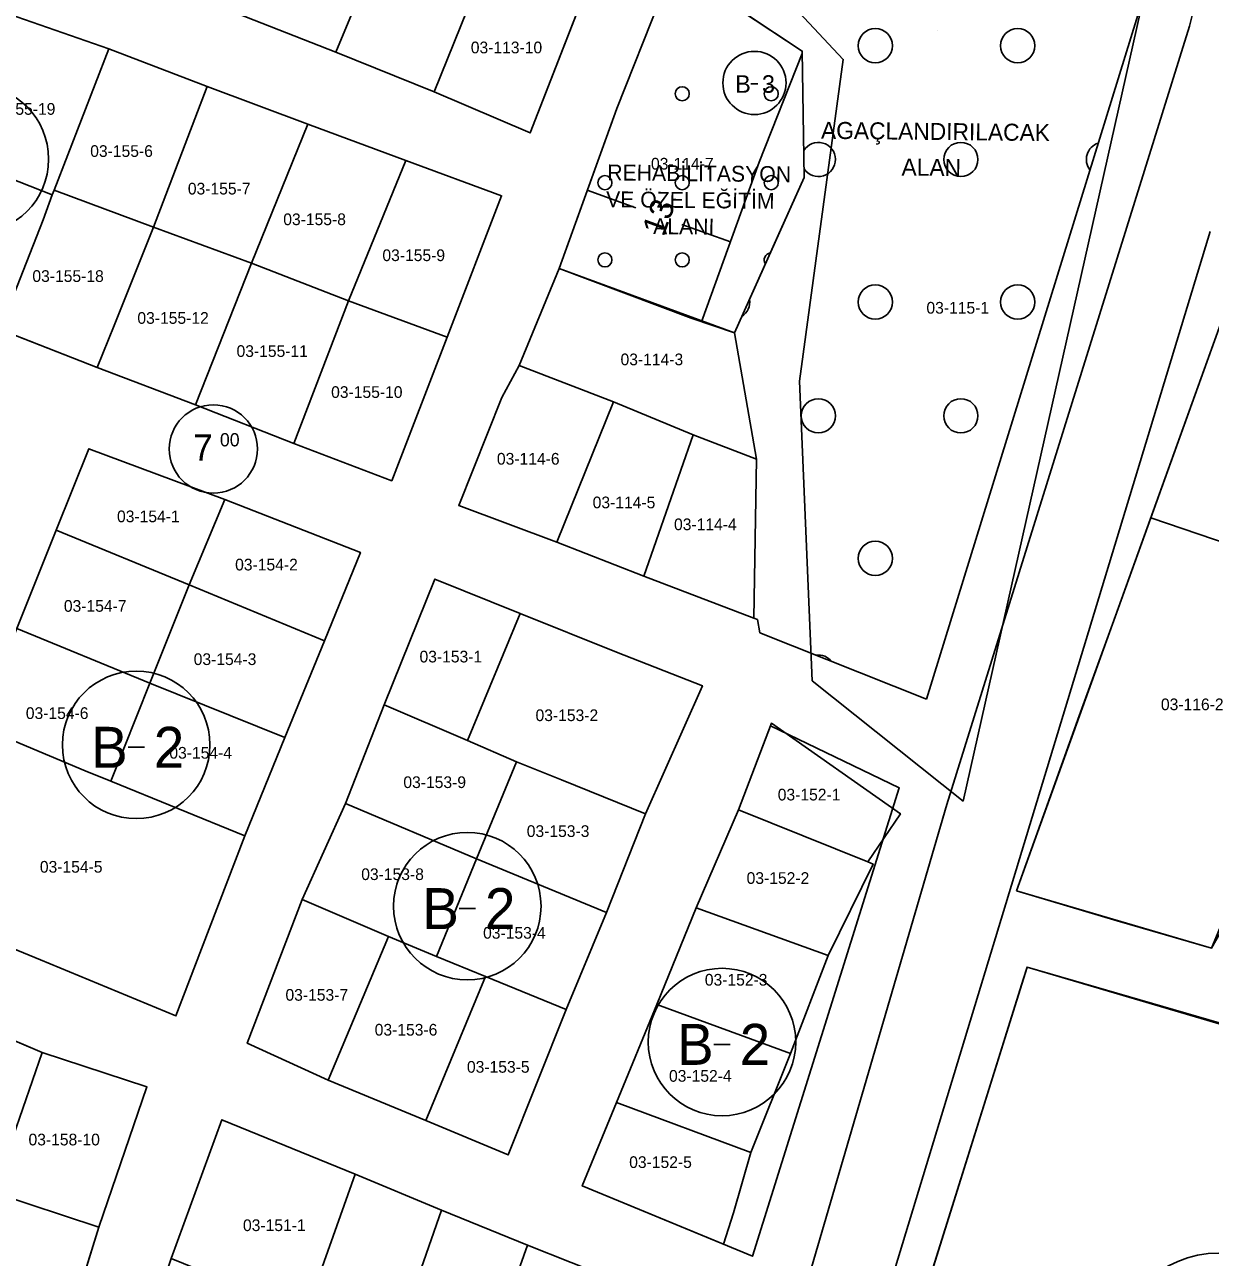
# Model space of a CAD drawing. Extents: x 413946 to 415528, y 4453939 to 4454944.
# Drawn here: x 414770 to 414871.3, y 4454188.1 to 4454293.5 of the extents above; entities that cross this region are included whole.
import ezdxf

# ---------------------------------------------------------------- set-up
doc = ezdxf.new("R2010")
doc.units = 0
for name, color, linetype in [('0_KADASTRO', 7, 'Continuous'), ('Level 20', 7, 'Continuous'), ('Level 27', 7, 'Continuous'), ('Level 28', 7, 'Continuous'), ('Level 29', 7, 'Continuous'), ('Level 33', 7, 'Continuous'), ('Level 34', 7, 'Continuous'), ('Level 42', 7, 'Continuous'), ('Level 43', 7, 'Continuous'), ('Level 54', 7, 'Continuous'), ('Level 62', 7, 'Continuous'), ('SEMBOL', 7, 'Continuous'), ('SNR_FONKSIYON', 7, 'Continuous'), ('SNR_YAPIYAK', 7, 'Continuous')]:
    doc.layers.add(name, color=color, linetype=linetype)

msp = doc.modelspace()

# ---------------------------------------------------------------- linework, layer by layer
at = {"layer": '0_KADASTRO'}
for points in [[(414832.03, 4454298.98), (414838.1, 4454302.72), (414846.56, 4454310.73), (414850.2, 4454326.97), (414865.66, 4454296.04), (414850.19, 4454227.12), (414837.29, 4454237.41), (414836.22, 4454262.99), (414839.96, 4454290.49)], [(414788.17, 4454294.42), (414793.15, 4454306.88), (414801.8, 4454303.57), (414796.61, 4454291.12)], [(414796.61, 4454291.12), (414801.8, 4454303.57), (414810.12, 4454300.36), (414805, 4454287.71)], [(414805, 4454287.71), (414810.12, 4454300.36), (414818.3, 4454297.33), (414813.2, 4454284.21)], [(414815.68, 4454272.63), (414818.73, 4454281.09), (414820.62, 4454286.31), (414824.34, 4454295.73), (414827.17, 4454297.35), (414836.45, 4454291.2), (414836.62, 4454280.41), (414834.34, 4454275.32), (414830.66, 4454267.12), (414826.97, 4454268.38)], [(414763.9, 4454282.25), (414764.12, 4454282.88), (414765.37, 4454286.01), (414768.71, 4454294.36), (414777.22, 4454291.39), (414772.55, 4454279.33), (414772.39, 4454278.91)], [(414772.55, 4454279.33), (414777.22, 4454291.39), (414785.63, 4454288.19), (414781.05, 4454276.16)], [(414781.05, 4454276.16), (414785.63, 4454288.19), (414794.22, 4454284.95), (414789.42, 4454273.08)], [(414789.42, 4454273.08), (414794.22, 4454284.95), (414802.59, 4454281.85), (414797.69, 4454269.86)], [(414756.22, 4454272.04), (414760.92, 4454283.99), (414764.12, 4454282.88), (414763.9, 4454282.25), (414772.39, 4454278.91), (414771.6, 4454276.78), (414767.95, 4454267.42), (414767.49, 4454267.6), (414758.76, 4454271.04)], [(414797.69, 4454269.86), (414802.59, 4454281.85), (414810.77, 4454278.84), (414806.13, 4454266.76)], [(414767.95, 4454267.42), (414771.6, 4454276.78), (414772.39, 4454278.91), (414772.55, 4454279.33), (414781.05, 4454276.16), (414777.69, 4454267.75), (414776.23, 4454264.18)], [(414776.23, 4454264.18), (414777.69, 4454267.75), (414781.05, 4454276.16), (414789.42, 4454273.08), (414784.62, 4454260.99)], [(414784.62, 4454260.99), (414789.42, 4454273.08), (414797.69, 4454269.86), (414793.03, 4454257.69)], [(414812.27, 4454264.34), (414815.68, 4454272.63), (414826.97, 4454268.38), (414830.66, 4454267.12), (414832.54, 4454256.34), (414827.14, 4454258.41), (414820.34, 4454261.23)], [(414793.03, 4454257.69), (414797.69, 4454269.86), (414806.13, 4454266.76), (414801.39, 4454254.49)], [(414866.22, 4454251.33), (414873.1, 4454270.41), (414882.7, 4454267.64), (414875.68, 4454248.11)], [(414854.74, 4454219.46), (414860.12, 4454234.41), (414863.17, 4454242.88), (414866.22, 4454251.33), (414875.68, 4454248.11), (414882.7, 4454267.64), (414886.54, 4454266.53), (414890.57, 4454260.69), (414884.15, 4454245.23), (414880.7, 4454236.93), (414877.25, 4454228.62), (414871.98, 4454215.94), (414871.41, 4454214.55), (414863.36, 4454216.9)], [(414807.11, 4454252.37), (414810.8, 4454261.62), (414812.27, 4454264.34), (414820.34, 4454261.23), (414815.48, 4454249.26)], [(414815.48, 4454249.26), (414820.34, 4454261.23), (414827.14, 4454258.41), (414822.93, 4454246.35)], [(414822.93, 4454246.35), (414827.14, 4454258.41), (414832.54, 4454256.34), (414832.32, 4454242.75)], [(414772.73, 4454250.28), (414775.51, 4454257.23), (414787.12, 4454252.89), (414784.08, 4454245.59)], [(414784.08, 4454245.59), (414787.12, 4454252.89), (414798.71, 4454248.37), (414795.63, 4454240.82)], [(414769.36, 4454241.86), (414772.73, 4454250.28), (414784.08, 4454245.59), (414780.73, 4454237.2)], [(414780.73, 4454237.2), (414784.08, 4454245.59), (414795.63, 4454240.82), (414792.25, 4454232.56)], [(414800.74, 4454235.36), (414805.08, 4454246.09), (414812.37, 4454243.14), (414807.85, 4454232.29)], [(414807.85, 4454232.29), (414812.37, 4454243.14), (414820.6, 4454239.86), (414827.92, 4454236.98), (414823.05, 4454226.04), (414815.88, 4454228.93), (414812.04, 4454230.47)], [(414766.04, 4454233.56), (414769.36, 4454241.86), (414780.73, 4454237.2), (414777.4, 4454228.84), (414775.2, 4454229.71)], [(414777.4, 4454228.84), (414780.73, 4454237.2), (414792.25, 4454232.56), (414788.83, 4454224.17)], [(414797.44, 4454226.92), (414800.74, 4454235.36), (414807.85, 4454232.29), (414812.04, 4454230.47), (414808.64, 4454222.18)], [(414831.02, 4454226.38), (414833.82, 4454233.78), (414844.84, 4454226.04), (414842.05, 4454221.95)], [(414759.79, 4454218.33), (414762.79, 4454225.66), (414766.04, 4454233.56), (414775.2, 4454229.71), (414777.4, 4454228.84), (414788.83, 4454224.17), (414785.8, 4454216.2), (414782.95, 4454208.77), (414771.37, 4454213.55)], [(414808.64, 4454222.18), (414812.04, 4454230.47), (414815.88, 4454228.93), (414823.05, 4454226.04), (414819.72, 4454217.62)], [(414793.73, 4454218.72), (414797.44, 4454226.92), (414808.64, 4454222.18), (414805.22, 4454213.86), (414801.1, 4454215.56)], [(414827.39, 4454218), (414831.02, 4454226.38), (414842.05, 4454221.95), (414842.5, 4454221.74), (414838.66, 4454213.93)], [(414805.22, 4454213.86), (414808.64, 4454222.18), (414819.72, 4454217.62), (414816.28, 4454209.32), (414809.4, 4454212.13)], [(414789.05, 4454206.43), (414793.73, 4454218.72), (414801.1, 4454215.56), (414795.95, 4454203.28)], [(414824.03, 4454209.74), (414827.39, 4454218), (414838.66, 4454213.93), (414835.46, 4454205.55)], [(414795.95, 4454203.28), (414801.1, 4454215.56), (414805.22, 4454213.86), (414809.4, 4454212.13), (414804.29, 4454199.85)], [(414837.9, 4454152.37), (414841.59, 4454167.97), (414850.85, 4454197.57), (414855.33, 4454211.88), (414855.66, 4454212.94), (414874.02, 4454207.6), (414876.77, 4454206.53), (414913.67, 4454192.21), (414892.7, 4454138.17)], [(414804.29, 4454199.85), (414809.4, 4454212.13), (414816.28, 4454209.32), (414811.34, 4454196.9)], [(414820.58, 4454201.37), (414824.03, 4454209.74), (414835.46, 4454205.55), (414832.06, 4454197.11)], [(414758.86, 4454196.63), (414763.25, 4454209.19), (414771.53, 4454205.64), (414767.38, 4454193.69)], [(414767.38, 4454193.69), (414771.53, 4454205.64), (414780.48, 4454202.71), (414776.36, 4454190.71)], [(414817.66, 4454194.25), (414820.58, 4454201.37), (414832.06, 4454197.11), (414830.57, 4454191.94), (414829.72, 4454189.27)], [(414782.54, 4454188.05), (414786.88, 4454199.9), (414798.27, 4454195.26), (414794.06, 4454183.37), (414789.48, 4454185.23)], [(414794.06, 4454183.37), (414798.27, 4454195.26), (414805.65, 4454192.19), (414801.51, 4454180.34), (414798.22, 4454181.68)], [(414763.1, 4454181.29), (414767.38, 4454193.69), (414776.36, 4454190.71), (414772.34, 4454177.79)], [(414801.51, 4454180.34), (414805.65, 4454192.19), (414812.97, 4454189.19), (414808.79, 4454177.39), (414807.52, 4454177.9)], [(414808.79, 4454177.39), (414812.97, 4454189.19), (414820.45, 4454186.23), (414816.3, 4454174.34)]]:
    msp.add_lwpolyline(points, close=True, dxfattribs=at)
at = {"layer": 'Level 20'}
for p, q in [((414818.09, 4454279.31), (414822.23, 4454277.82)), ((414830.32, 4454274.9), (414826.18, 4454276.39))]:
    msp.add_line(p, q, dxfattribs=at)
at = {"layer": 'Level 27'}
for p, q in [((414823.57, 4454310.85), (414813.2, 4454284.21)), ((414820.62, 4454286.31), (414824.34, 4454295.73)), ((414768.71, 4454294.36), (414777.22, 4454291.39)), ((414796.61, 4454291.12), (414788.17, 4454294.42)), ((414777.22, 4454291.39), (414785.63, 4454288.19)), ((414805, 4454287.71), (414796.61, 4454291.12)), ((414785.63, 4454288.19), (414794.22, 4454284.95)), ((414813.2, 4454284.21), (414805, 4454287.71)), ((414815.68, 4454272.63), (414820.62, 4454286.31)), ((414794.22, 4454284.95), (414802.59, 4454281.85)), ((414802.59, 4454281.85), (414810.77, 4454278.84)), ((414810.77, 4454278.84), (414806.13, 4454266.76)), ((414812.27, 4454264.34), (414815.68, 4454272.63)), ((414776.23, 4454264.18), (414767.49, 4454267.6)), ((414806.13, 4454266.76), (414801.39, 4454254.49)), ((414810.8, 4454261.62), (414812.27, 4454264.34)), ((414784.62, 4454260.99), (414776.23, 4454264.18)), ((414807.11, 4454252.37), (414810.8, 4454261.62)), ((414793.03, 4454257.69), (414784.62, 4454260.99)), ((414772.73, 4454250.28), (414775.51, 4454257.23)), ((414775.51, 4454257.23), (414787.12, 4454252.89)), ((414801.39, 4454254.49), (414793.03, 4454257.69)), ((414787.12, 4454252.89), (414798.71, 4454248.37)), ((414815.48, 4454249.26), (414807.11, 4454252.37)), ((414769.36, 4454241.86), (414772.73, 4454250.28)), ((414822.93, 4454246.35), (414815.48, 4454249.26)), ((414798.71, 4454248.37), (414795.63, 4454240.82)), ((414800.74, 4454235.36), (414805.08, 4454246.09)), ((414805.08, 4454246.09), (414812.37, 4454243.14)), ((414832.32, 4454242.75), (414822.93, 4454246.35)), ((414812.37, 4454243.14), (414820.6, 4454239.86)), ((414832.62, 4454242.63), (414832.32, 4454242.75)), ((414795.63, 4454240.82), (414792.25, 4454232.56)), ((414820.6, 4454239.86), (414827.92, 4454236.98)), ((414827.92, 4454236.98), (414823.05, 4454226.04)), ((414797.44, 4454226.92), (414800.74, 4454235.36)), ((414831.02, 4454226.38), (414833.73, 4454233.55)), ((414833.73, 4454233.55), (414844.74, 4454228.27)), ((414792.25, 4454232.56), (414788.83, 4454224.17)), ((414793.73, 4454218.72), (414797.44, 4454226.92)), ((414823.05, 4454226.04), (414819.72, 4454217.62)), ((414827.39, 4454218), (414831.02, 4454226.38)), ((414788.83, 4454224.17), (414785.8, 4454216.2)), ((414771.37, 4454213.55), (414759.79, 4454218.33)), ((414789.05, 4454206.43), (414793.73, 4454218.72)), ((414824.03, 4454209.74), (414827.39, 4454218)), ((414819.72, 4454217.62), (414816.28, 4454209.32)), ((414785.8, 4454216.2), (414782.95, 4454208.77)), ((414782.95, 4454208.77), (414771.37, 4454213.55)), ((414820.58, 4454201.37), (414824.03, 4454209.74)), ((414763.25, 4454209.19), (414771.53, 4454205.64)), ((414816.28, 4454209.32), (414811.34, 4454196.9)), ((414795.95, 4454203.28), (414789.05, 4454206.43)), ((414771.53, 4454205.64), (414780.48, 4454202.71)), ((414804.29, 4454199.85), (414795.95, 4454203.28)), ((414780.48, 4454202.71), (414776.36, 4454190.71)), ((414817.66, 4454194.25), (414820.58, 4454201.37)), ((414782.54, 4454188.05), (414786.88, 4454199.9)), ((414786.88, 4454199.9), (414798.27, 4454195.26)), ((414811.34, 4454196.9), (414804.29, 4454199.85)), ((414798.27, 4454195.26), (414805.65, 4454192.19)), ((414832.21, 4454188.24), (414817.66, 4454194.25)), ((414805.65, 4454192.19), (414812.97, 4454189.19)), ((414776.36, 4454190.71), (414772.34, 4454177.79)), ((414812.97, 4454189.19), (414820.45, 4454186.23))]:
    msp.add_line(p, q, dxfattribs=at)
at = {"layer": 'Level 28'}
for p, q in [((414854.74, 4454219.46), (414873.1, 4454270.41)), ((414832.82, 4454241.49), (414832.62, 4454242.63)), ((414847.08, 4454235.84), (414832.82, 4454241.49)), ((414871.41, 4454214.55), (414854.74, 4454219.47)), ((414841.67, 4454168.23), (414855.66, 4454212.94)), ((414855.66, 4454212.94), (414873.99, 4454207.53))]:
    msp.add_line(p, q, dxfattribs=at)
at = {"layer": 'Level 29'}
for p, q in [((414865.66, 4454296.04), (414847.08, 4454235.84)), ((414844.74, 4454228.27), (414832.21, 4454188.24))]:
    msp.add_line(p, q, dxfattribs=at)
at = {"layer": 'Level 34'}
msp.add_lwpolyline([(414854.74, 4454219.46), (414871.41, 4454214.55), (414872.15, 4454215.87), (414903.18, 4454203.7), (414934.11, 4454191.68), (414948.07, 4454183.07), (414956.72, 4454177.69), (414957.04, 4454177.56), (414957.39, 4454177.55), (414957.72, 4454177.66), (414957.99, 4454177.87), (414958.17, 4454178.17), (414958.25, 4454178.51), (414958.2, 4454178.85), (414958.03, 4454179.16), (414935.35, 4454208.13), (414915.56, 4454233.53), (414892.66, 4454262.67), (414886.54, 4454266.53), (414873.1, 4454270.41)], close=True, dxfattribs=at)
at = {"layer": 'Level 42'}
for centre in [(414842.69, 4454291.66), (414854.86, 4454291.66), (414850, 4454281.94), (414842.69, 4454269.76), (414854.86, 4454269.76), (414837.83, 4454260.04), (414850, 4454260.04), (414842.69, 4454247.86)]:
    msp.add_circle(centre, 1.46, dxfattribs=at)
for centre, start, end in [((414837.83, 4454281.94), 213.1955, 148.63), ((414862.18, 4454281.94), 107.6978, 217.9857), ((414830.51, 4454269.76), 302.6294, 9.0773), ((414837.83, 4454238.14), 38.7646, 98.0303)]:
    msp.add_arc(centre, 1.46, start, end, dxfattribs=at)
at = {"layer": 'Level 43'}
for centre in [(414826.2, 4454287.56), (414833.8, 4454287.56), (414819.6, 4454279.96), (414826.2, 4454279.96), (414833.8, 4454279.96), (414819.6, 4454273.36), (414826.2, 4454273.36)]:
    msp.add_circle(centre, 0.6, dxfattribs=at)
msp.add_arc((414833.8, 4454273.36), 0.6, 97.3832, 214.3235, dxfattribs=at)
at = {"layer": 'Level 54'}
for p, q in [((414848.02, 4454292.98), (414848.02, 4454292.98)), ((414826.56, 4454287.83), (414826.56, 4454287.83))]:
    msp.add_line(p, q, dxfattribs=at)
for points in [[(414823.57, 4454310.85), (414813.2, 4454284.21), (414805, 4454287.71), (414796.61, 4454291.12), (414788.17, 4454294.42), (414784.17, 4454296.03), (414771.34, 4454300.86), (414771.15, 4454300.41), (414762.88, 4454303.65), (414763.03, 4454304.04), (414753.68, 4454307.62), (414744.35, 4454311.27), (414736.35, 4454314.29), (414748.56, 4454342.46), (414757.51, 4454338.73), (414765.87, 4454335.39), (414774.06, 4454331.58), (414774.14, 4454331.82), (414782.43, 4454327.95), (414782.15, 4454327.33), (414790.62, 4454324.21), (414799.23, 4454320.55), (414807.21, 4454317.43), (414815.49, 4454314.06)], [(414794.22, 4454284.95), (414802.59, 4454281.85), (414810.77, 4454278.84), (414806.13, 4454266.76), (414801.39, 4454254.49), (414793.03, 4454257.69), (414784.62, 4454260.99), (414776.23, 4454264.18), (414767.49, 4454267.6), (414758.76, 4454271.04), (414750.01, 4454274.48), (414741.25, 4454277.89), (414732.41, 4454281.37), (414723.79, 4454284.57), (414728.36, 4454296.14), (414733.7, 4454308.38), (414741.83, 4454305.09), (414751.12, 4454301.46), (414760.39, 4454297.62), (414768.71, 4454294.36), (414777.22, 4454291.39), (414785.63, 4454288.19)], [(414832.54, 4454256.34), (414832.32, 4454242.75), (414822.93, 4454246.35), (414815.48, 4454249.26), (414807.11, 4454252.37), (414810.8, 4454261.62), (414812.27, 4454264.34), (414815.68, 4454272.63), (414830.66, 4454267.12)], [(414759.79, 4454218.33), (414766.04, 4454233.56), (414769.36, 4454241.86), (414772.73, 4454250.28), (414775.51, 4454257.23), (414787.12, 4454252.89), (414798.71, 4454248.37), (414795.63, 4454240.82), (414792.25, 4454232.56), (414788.83, 4454224.17), (414785.8, 4454216.2), (414782.95, 4454208.77), (414771.37, 4454213.55)], [(414804.29, 4454199.85), (414795.95, 4454203.28), (414789.05, 4454206.43), (414793.73, 4454218.72), (414797.44, 4454226.92), (414800.74, 4454235.36), (414805.08, 4454246.09), (414812.37, 4454243.14), (414820.6, 4454239.86), (414827.92, 4454236.98), (414823.05, 4454226.04), (414819.72, 4454217.62), (414816.28, 4454209.32), (414811.34, 4454196.9)], [(414824.03, 4454209.74), (414827.39, 4454218), (414831.02, 4454226.38), (414833.73, 4454233.55), (414844.74, 4454228.27), (414832.21, 4454188.24), (414817.66, 4454194.25), (414820.58, 4454201.37)], [(414756.36, 4454212.12), (414763.25, 4454209.19), (414771.53, 4454205.64), (414780.48, 4454202.71), (414776.36, 4454190.71), (414772.34, 4454177.79), (414763.1, 4454181.29), (414754.66, 4454184.35), (414747.11, 4454187.16), (414739.45, 4454189.83), (414731.99, 4454192.4), (414724.88, 4454194.83), (414717.52, 4454197.57), (414717.59, 4454197.75), (414710.13, 4454200.48), (414702.72, 4454203.33), (414695.97, 4454205.8), (414706.25, 4454232.5), (414712.27, 4454230.06), (414719.4, 4454227.19), (414726.78, 4454224.24), (414734.16, 4454221.25), (414741.06, 4454218.5), (414748.9, 4454215.47)], [(414905.26, 4454170.2), (414892.59, 4454137.92), (414837.84, 4454152.11), (414841.67, 4454168.23), (414855.66, 4454212.94), (414873.99, 4454207.53), (414913.66, 4454192.2), (414909.33, 4454180.88)], [(414824.06, 4454158.22), (414813, 4454162.23), (414810.91, 4454162.59), (414809.62, 4454162.98), (414803.44, 4454165.74), (414794.21, 4454169.63), (414785.34, 4454172.91), (414785.27, 4454172.72), (414778.22, 4454175.28), (414782.54, 4454188.05), (414786.88, 4454199.9), (414798.27, 4454195.26), (414805.65, 4454192.19), (414812.97, 4454189.19), (414820.45, 4454186.23), (414830.84, 4454182.13)]]:
    msp.add_lwpolyline(points, close=True, dxfattribs=at)
at = {"layer": 'Level 62'}
for points in [[(414869.54, 4454293.32), (414869.77, 4454294.25), (414869.89, 4454295.2), (414869.89, 4454296.16), (414869.78, 4454297.11), (414869.55, 4454298.05), (414869.22, 4454298.94), (414868.78, 4454299.8), (414868.24, 4454300.59)], [(414869.53, 4454293.32), (414848.8, 4454226.83), (414837.23, 4454187.29), (414822.07, 4454133.17)], [(414828.72, 4454124.63), (414830.65, 4454134.81), (414841.98, 4454179.28), (414871.31, 4454275.78)]]:
    msp.add_lwpolyline(points, dxfattribs=at)
at = {"layer": 'SEMBOL'}
for p, q in [((414832.07, 4454288.39), (414832.67, 4454288.39)), ((414778.86, 4454231.72), (414780.26, 4454231.72)), ((414807.14, 4454217.94), (414808.54, 4454217.94)), ((414828.9, 4454206.34), (414830.3, 4454206.34))]:
    msp.add_line(p, q, dxfattribs=at)
for centre, radius in [((414832.37, 4454288.48), 2.7), ((414765.78, 4454281.97), 6.3), ((414786.15, 4454257.21), 3.77), ((414779.56, 4454231.93), 6.3), ((414807.84, 4454218.15), 6.3), ((414829.6, 4454206.54), 6.3), ((414872.04, 4454179.51), 9)]:
    msp.add_circle(centre, radius, dxfattribs=at)
at = {"layer": 'SNR_FONKSIYON'}
for p, q in [((414827.17, 4454297.35), (414836.45, 4454291.2)), ((414836.45, 4454291.2), (414836.62, 4454280.41)), ((414836.62, 4454280.41), (414830.66, 4454267.12)), ((414830.66, 4454267.12), (414832.54, 4454256.34)), ((414832.54, 4454256.34), (414832.32, 4454242.75))]:
    msp.add_line(p, q, dxfattribs=at)
msp.add_lwpolyline([(414830.66, 4454267.12), (414826.97, 4454268.38), (414815.68, 4454272.63)], dxfattribs=at)
at = {"layer": 'SNR_YAPIYAK'}
msp.add_lwpolyline([(414827.86, 4454268.08), (414832.78, 4454281.71), (414836.45, 4454290.99)], dxfattribs=at)

# ---------------------------------------------------------------- texts
at = {"layer": '0_KADASTRO'}
for s, p in [('03-113-10', (414808.14, 4454291.01)), ('03-155-19', (414766.56, 4454285.76)), ('03-155-6', (414775.63, 4454282.16)), ('03-114-7', (414823.53, 4454281.08)), ('03-155-7', (414783.97, 4454278.95)), ('03-155-8', (414792.12, 4454276.33)), ('03-155-9', (414800.59, 4454273.26)), ('03-155-18', (414770.69, 4454271.48)), ('03-115-1', (414847.06, 4454268.77)), ('03-155-12', (414779.66, 4454267.9)), ('03-155-11', (414788.13, 4454265.07)), ('03-114-3', (414820.93, 4454264.36)), ('03-155-10', (414796.21, 4454261.57)), ('03-114-6', (414810.37, 4454255.87)), ('03-114-5', (414818.55, 4454252.14)), ('03-154-1', (414777.92, 4454250.95)), ('03-114-4', (414825.5, 4454250.27)), ('03-154-2', (414788.01, 4454246.83)), ('03-154-7', (414773.38, 4454243.3)), ('03-154-3', (414784.47, 4454238.75)), ('03-153-1', (414803.76, 4454238.97)), ('03-116-2', (414867.09, 4454234.89)), ('03-154-6', (414770.13, 4454234.14)), ('03-153-2', (414813.67, 4454233.96)), ('03-154-4', (414782.39, 4454230.75)), ('03-153-9', (414802.38, 4454228.24)), ('03-152-1', (414834.36, 4454227.18)), ('03-153-3', (414812.92, 4454224.06)), ('03-154-5', (414771.33, 4454221.01)), ('03-153-8', (414798.78, 4454220.38)), ('03-152-2', (414831.7, 4454220.05)), ('03-153-4', (414809.19, 4454215.37)), ('03-152-3', (414828.13, 4454211.36)), ('03-153-7', (414792.31, 4454210.07)), ('03-153-6', (414799.93, 4454207.09)), ('03-153-5', (414807.81, 4454203.92)), ('03-152-4', (414825.07, 4454203.15)), ('03-158-10', (414770.36, 4454197.71)), ('03-152-5', (414821.67, 4454195.78)), ('03-151-1', (414788.68, 4454190.39))]:
    msp.add_text(s, height=1, dxfattribs=at).set_placement(p)
at = {"layer": 'Level 20'}
msp.add_text('13', height=2, rotation=70.1384, dxfattribs=at).set_placement((414824.61, 4454275.28))
at = {"layer": 'Level 33'}
for s, height, p in [('AGAÇLANDIRILACAK', 1.4536, (414838.05, 4454283.71)), ('REHABİLİTASYON', 1.3545, (414819.79, 4454280.16)), ('ALAN', 1.454, (414844.93, 4454280.57)), ('VE ÖZEL EĞİTİM', 1.3545, (414819.69, 4454277.87)), ('ALANI', 1.354, (414823.71, 4454275.57))]:
    msp.add_text(s, height=height, rotation=359.4136, dxfattribs=at).set_placement(p)
at = {"layer": 'SEMBOL'}
for s, height, p in [('B', 1.5, (414830.72, 4454287.64)), ('3', 1.5, (414833.01, 4454287.64)), ('7', 2.26, (414784.42, 4454256.2)), ('00', 1.131, (414786.71, 4454257.43)), ('B', 3.5, (414775.71, 4454229.97)), ('2', 3.5, (414781.06, 4454229.97)), ('B', 3.5, (414804, 4454216.19)), ('2', 3.5, (414809.35, 4454216.19)), ('B', 3.5, (414825.76, 4454204.59)), ('2', 3.5, (414831.11, 4454204.59))]:
    msp.add_text(s, height=height, dxfattribs=at).set_placement(p)

doc.saveas('drawing.dxf')
